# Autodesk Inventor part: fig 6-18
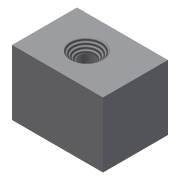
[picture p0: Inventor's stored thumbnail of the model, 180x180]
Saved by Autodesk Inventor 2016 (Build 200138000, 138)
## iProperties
Created: 2009-09
Part Number: fig 6-18
Document SubType Name: Modeling
Designer: Sham
Density: 1 g/cm^3
Material: Generic
Appearance: Default
Author: Sham
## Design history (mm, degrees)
sketch "Sketch1"
  geometry: L1 (-28, 20)-(0, 20); L2 (0, 20)-(0, 0); L3 (0, 0)-(-28, 0); L4 (-28, 0)-(-28, 20)
  constraints: 8 end point, 2 parallel, 1 horizontal, 1 perpendicular
extrude "Extrusion1" new body sketch "Sketch1" distance "d0" = 20; taper "d1" = 0 deg
hole "Hole1" diameter "d4" = 5; stored, may be unused: countersink angle "d8" = 90 deg, drill point angle "d10" = 118 deg; dims "d2" = 10, "d3" = 15, "d5" = 5.946, "d6" = 10, "d7" = 3, "d9" = 15, "d11" = 0.62479, "d12" = 5.994
thread "Thread1" dims "d13" = 10, "d14" = 0
body "Solid1"
